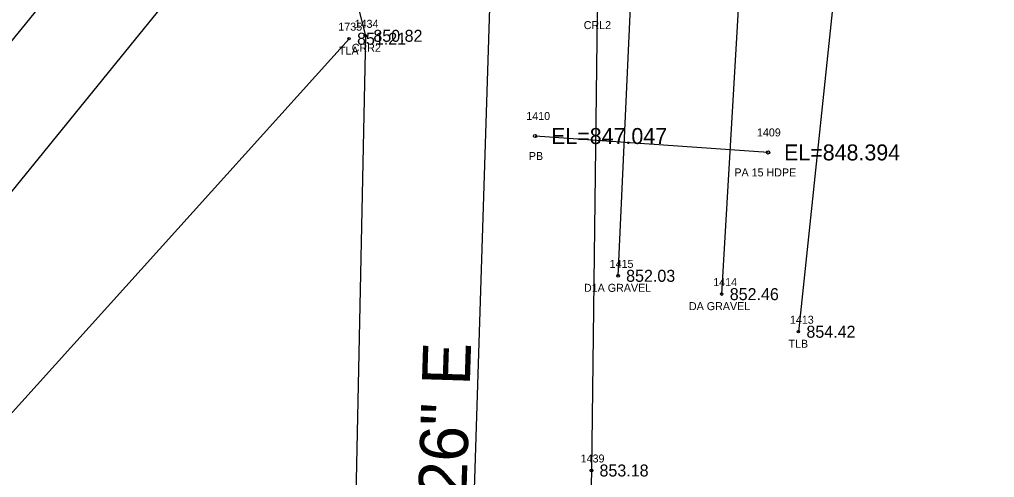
# Model space of a CAD drawing. Extents: x 1448136 to 1453623, y 1125056 to 1128842.
# Drawn here: x 1450680.5 to 1450802.4, y 1126844.9 to 1126902.1 of the extents above; entities that cross this region are included whole.
import ezdxf

# ---------------------------------------------------------------- set-up
doc = ezdxf.new("R2010")
doc.units = 0
for name, color, linetype in [('RD_EX_DR_Pipe', 7, 'Continuous'), ('RD_EX_DR_Pipe_txCode', 7, 'Continuous'), ('RD_EX_Driveway', 7, 'Continuous'), ('RD_EX_Driveway_txCode', 7, 'Continuous'), ('RD_EX_H2O', 7, 'Continuous'), ('RD_EX_H2O_txCode', 7, 'Continuous'), ('RD_EX_Road', 7, 'Continuous'), ('RD_EX_TX_Driveway_ELEV', 7, 'Continuous'), ('RD_EX_TX_H2O_ELEV', 7, 'Continuous'), ('RD_EX_TX_VEG_ELEV', 7, 'Continuous'), ('RD_EX_VEG', 7, 'Continuous'), ('RD_EX_VEG_txCode', 7, 'Continuous'), ('RD_HC_Cl', 7, 'Continuous'), ('RD_HC_Data', 7, 'Continuous'), ('RD_SMD_Locator', 7, 'Continuous'), ('RD_TX_Pipe_ElevEX', 7, 'Continuous')]:
    doc.layers.add(name, color=color, linetype=linetype)

msp = doc.modelspace()

# ---------------------------------------------------------------- linework, layer by layer
at = {"layer": 'RD_EX_DR_Pipe'}
msp.add_line((1450774.06, 1126885.52), (1450744.94, 1126887.57), dxfattribs=at)
at = {"layer": 'RD_EX_Driveway'}
for points in [[(1450768.27, 1126867.8), (1450770.43, 1126904.88), (1450777.45, 1126940.44), (1450786.03, 1126986.46)], [(1450755.32, 1126870.09), (1450756.91, 1126904.63), (1450765.18, 1126943.07), (1450766.81, 1126971.06), (1450764.58, 1126975.93), (1450758.82, 1126979.05), (1450762.34, 1126983.69)]]:
    msp.add_lwpolyline(points, dxfattribs=at)
at = {"layer": 'RD_EX_H2O'}
for points in [[(1450745.7, 1126955.23), (1450760.07, 1126934.18), (1450752.7, 1126902.94), (1450751.99, 1126845.75), (1450749.84, 1126753.84), (1450765.55, 1126601.5), (1450766.35, 1126534.46), (1450772.79, 1126478.95), (1450780.13, 1126423.06)], [(1450718.26, 1126921.7), (1450723.73, 1126900.1), (1450722.53, 1126842.54), (1450724.68, 1126757.52), (1450723.65, 1126673.1), (1450740.73, 1126600.37), (1450742.26, 1126535.96), (1450738.15, 1126478.88), (1450753.63, 1126426.16)]]:
    msp.add_lwpolyline(points, dxfattribs=at)
at = {"layer": 'RD_EX_Road'}
msp.add_lwpolyline([(1450714.95, 1126923.13), (1450701.14, 1126907.32), (1450669.79, 1126868.73), (1450636.8, 1126831.17), (1450601.85, 1126795.93), (1450563.91, 1126763.21), (1450523.61, 1126734.27), (1450480.52, 1126708.45), (1450435.58, 1126686.64), (1450388.58, 1126668.75), (1450340.73, 1126655.01), (1450291.74, 1126645.33)], dxfattribs=at)
at = {"layer": 'RD_EX_VEG'}
for points in [[(1451989.54, 1126836.98), (1451893.84, 1126905.64), (1451857.37, 1126942.27), (1451815.22, 1126966.53), (1451772.51, 1126993.52), (1451734.11, 1127020.41), (1451632.2, 1127074.86), (1451559.17, 1127115.62), (1451479.78, 1127184.41), (1451388.57, 1127251.26), (1451326.32, 1127287.16), (1451271.86, 1127300.71), (1451149.57, 1127304.55), (1451077.69, 1127285.44), (1451030.08, 1127262.15), (1450963.08, 1127198.6), (1450901.46, 1127121.24), (1450895.95, 1127120.38), (1450805.01, 1126983.22), (1450785.34, 1126934.46), (1450777.85, 1126863.1)], [(1450721.69, 1126899.74), (1450618.05, 1126784.79), (1450569.37, 1126747.82), (1450532.41, 1126721.31), (1450453.22, 1126645.31), (1450404.4, 1126631.22)]]:
    msp.add_lwpolyline(points, dxfattribs=at)
at = {"layer": 'RD_HC_Cl'}
for p, q in [((1450930.04, 1127207.93), (1450648.85, 1126861.73)), ((1450734.48, 1126750.6), (1450739.89, 1126923.46))]:
    msp.add_line(p, q, dxfattribs=at)
at = {"layer": 'RD_SMD_Locator'}
for centre, radius in [((1450721.69, 1126899.74), 0.15), ((1450723.73, 1126900.1), 0.15), ((1450744.94, 1126887.57), 0.2), ((1450774.06, 1126885.52), 0.2), ((1450755.32, 1126870.09), 0.15), ((1450768.27, 1126867.8), 0.15), ((1450777.85, 1126863.1), 0.15), ((1450751.99, 1126845.75), 0.15)]:
    msp.add_circle(centre, radius, dxfattribs=at)

# ---------------------------------------------------------------- texts
at = {"layer": 'RD_EX_DR_Pipe_txCode'}
for s, p in [('1410', (1450743.84, 1126889.57)), ('1409', (1450772.67, 1126887.52)), ('PB', (1450744.16, 1126884.57)), ('PA 15 HDPE', (1450769.85, 1126882.52))]:
    msp.add_text(s, height=1, dxfattribs=at).set_placement(p)
at = {"layer": 'RD_EX_Driveway_txCode'}
for s, p in [('1415', (1450754.26, 1126871.09)), ('D1A GRAVEL', (1450751.05, 1126868.09)), ('1414', (1450767.21, 1126868.8)), ('DA GRAVEL', (1450764.17, 1126865.8))]:
    msp.add_text(s, height=1, dxfattribs=at).set_placement(p)
at = {"layer": 'RD_EX_H2O_txCode'}
for s, p in [('1434', (1450722.39, 1126901.1)), ('CRL2', (1450751.02, 1126900.94)), ('CRR2', (1450722.03, 1126898.1)), ('1439', (1450750.64, 1126846.75))]:
    msp.add_text(s, height=1, dxfattribs=at).set_placement(p)
at = {"layer": 'RD_EX_TX_Driveway_ELEV'}
for s, p in [('852.03', (1450756.32, 1126869.34)), ('852.46', (1450769.27, 1126867.05))]:
    msp.add_text(s, height=1.5, dxfattribs=at).set_placement(p)
at = {"layer": 'RD_EX_TX_H2O_ELEV'}
for s, p in [('850.82', (1450724.73, 1126899.35)), ('853.18', (1450752.99, 1126845))]:
    msp.add_text(s, height=1.5, dxfattribs=at).set_placement(p)
at = {"layer": 'RD_EX_TX_VEG_ELEV'}
for s, p in [('851.21', (1450722.69, 1126898.99)), ('854.42', (1450778.85, 1126862.35))]:
    msp.add_text(s, height=1.5, dxfattribs=at).set_placement(p)
at = {"layer": 'RD_EX_VEG_txCode'}
for s, p in [('1735', (1450720.35, 1126900.74)), ('TLA', (1450720.43, 1126897.74)), ('1413', (1450776.79, 1126864.1)), ('TLB', (1450776.61, 1126861.1))]:
    msp.add_text(s, height=1, dxfattribs=at).set_placement(p)
at = {"layer": 'RD_HC_Data'}
msp.add_text('N 1%%d 47\' 26" E', height=6, rotation=88.2094, dxfattribs=at).set_placement((1450735.39, 1126811.73))
at = {"layer": 'RD_TX_Pipe_ElevEX'}
for s, p in [('EL=847.047', (1450746.94, 1126886.57)), ('EL=848.394', (1450776.06, 1126884.52))]:
    msp.add_text(s, height=2, dxfattribs=at).set_placement(p)

doc.saveas('drawing.dxf')
